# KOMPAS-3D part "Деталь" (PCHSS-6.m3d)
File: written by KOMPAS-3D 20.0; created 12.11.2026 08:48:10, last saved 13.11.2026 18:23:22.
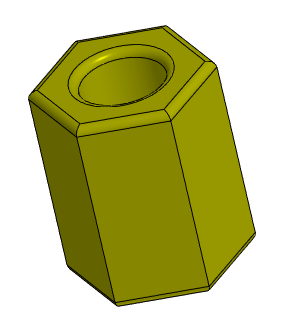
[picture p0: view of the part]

Document properties: Полное имя файла: D:\myProjects\Progect_esp32\box_compas\прочее\PCHSS-6.m3d

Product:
- Part/product: Деталь
    Масса: 0.000627349

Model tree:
1. Эскиз:1
2. Элемент выдавливания:1
     Расстояние 1 = 6
3. Эскиз:2  (with: Элемент выдавливания:1)
4. Элемент выдавливания:2
     Расстояние 2 = 6
5. Скругление:1  (with: Элемент выдавливания:1)
     Радиус = 0.25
